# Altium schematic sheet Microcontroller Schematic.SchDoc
size A; SheetNumber: 1; SheetTotal: 1
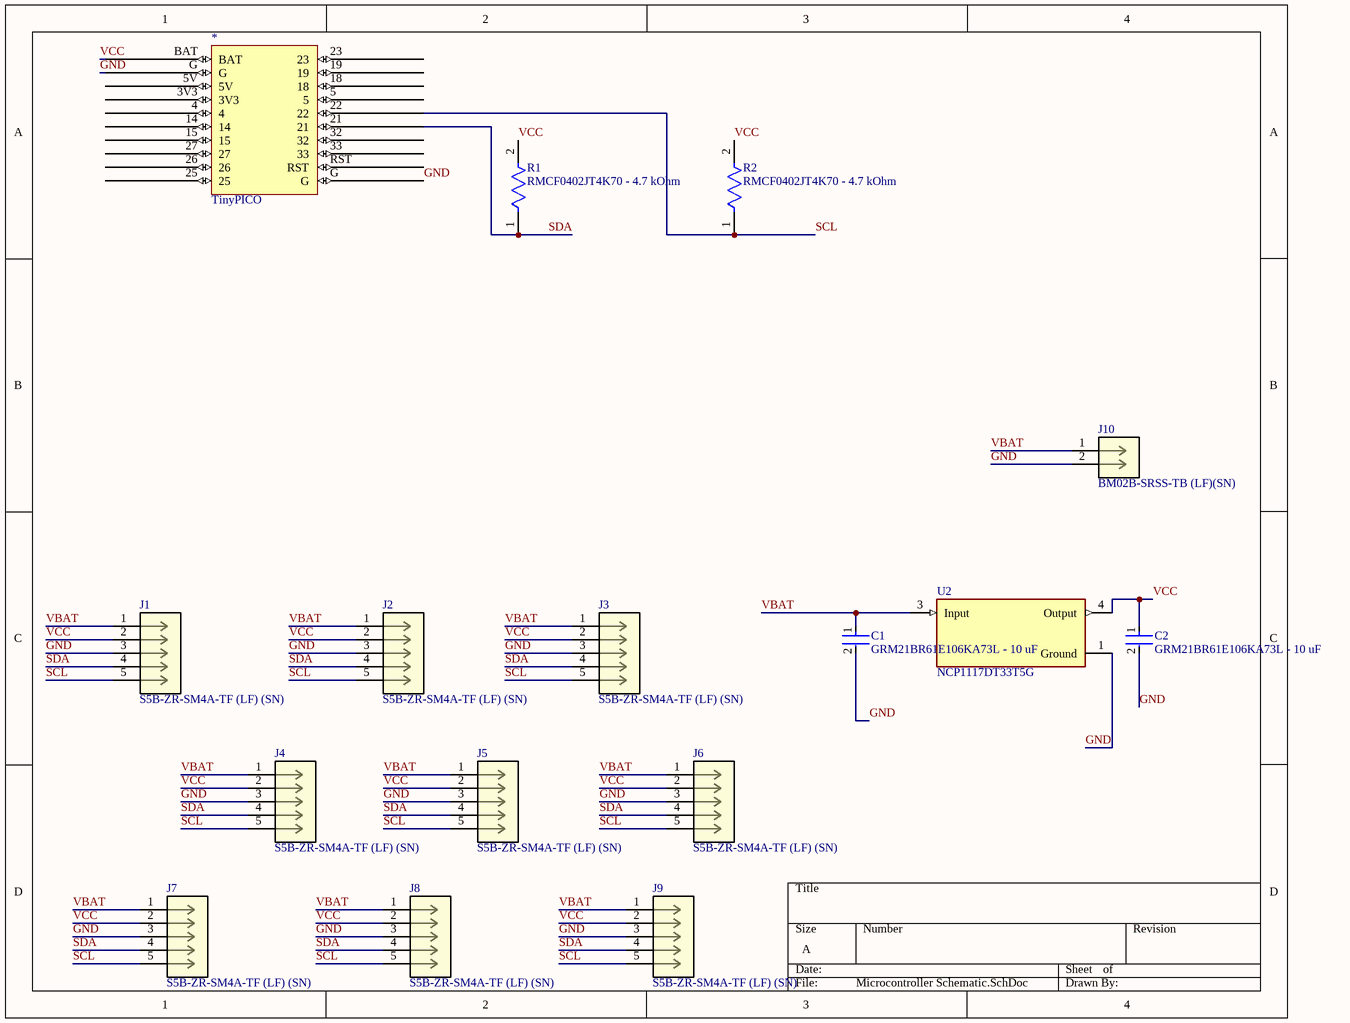
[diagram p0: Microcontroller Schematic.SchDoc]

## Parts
*  TinyPICO  [TinyPICO Board]
C1  GRM21BR61E106KA73L - 10 uF  [FP-GRM21B-0_15-IPC_C]
C2  GRM21BR61E106KA73L - 10 uF  [FP-GRM21B-0_15-IPC_C]
J1  S5B-ZR-SM4A-TF (LF) (SN)  [CONN_S5B-ZR-SM4A-TF_JST]
J2  S5B-ZR-SM4A-TF (LF) (SN)  [CONN_S5B-ZR-SM4A-TF_JST]
J3  S5B-ZR-SM4A-TF (LF) (SN)  [CONN_S5B-ZR-SM4A-TF_JST]
J4  S5B-ZR-SM4A-TF (LF) (SN)  [CONN_S5B-ZR-SM4A-TF_JST]
J5  S5B-ZR-SM4A-TF (LF) (SN)  [CONN_S5B-ZR-SM4A-TF_JST]
J6  S5B-ZR-SM4A-TF (LF) (SN)  [CONN_S5B-ZR-SM4A-TF_JST]
J7  S5B-ZR-SM4A-TF (LF) (SN)  [CONN_S5B-ZR-SM4A-TF_JST]
J8  S5B-ZR-SM4A-TF (LF) (SN)  [CONN_S5B-ZR-SM4A-TF_JST]
J9  S5B-ZR-SM4A-TF (LF) (SN)  [CONN_S5B-ZR-SM4A-TF_JST]
J10  BM02B-SRSS-TB (LF)(SN)  [CONN_BM02B-SRSS-TB_JST]
R1  RMCF0402JT4K70 - 4.7 kOhm  [FP-RMCF0402-MFG]
R2  RMCF0402JT4K70 - 4.7 kOhm  [FP-RMCF0402-MFG]
U2  NCP1117DT33T5G  [FP-369C-MFG]

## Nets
GND: *.G C1.2 C2.2 J1.3 J2.3 J3.3 J4.3 J5.3 J6.3 J7.3 J8.3 J9.3 J10.2 U2.1(Ground)
SCL: *.22 J1.5 J2.5 J3.5 J4.5 J5.5 J6.5 J7.5 J8.5 J9.5 R2.1
SDA: *.21 J1.4 J2.4 J3.4 J4.4 J5.4 J6.4 J7.4 J8.4 J9.4 R1.1
VBAT: C1.1 J1.1 J2.1 J3.1 J4.1 J5.1 J6.1 J7.1 J8.1 J9.1 J10.1 U2.3(Input)
VCC: *.BAT C2.1 J1.2 J2.2 J3.2 J4.2 J5.2 J6.2 J7.2 J8.2 J9.2 R1.2 R2.2 U2.4(Output)

Not connected (* = marked no-connect by the designer): * 3V3 4 5 5V 14 15 18 19 23 25 26 27 32 33 RST

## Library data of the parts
C1 C2 = CMP-2007-03541-2: Chip Multilayer Ceramic Capacitors for General Purpose, 0805, 10uF, X5R, 15%, 10%, 25V
J1-J9 = S5B-ZR-SM4A-TF (LF) (SN): No Description Available; Mfr_Name: JST
J10 = BM02B-SRSS-TB (LF)(SN): No Description Available; Mfr_Name: JST
R1 R2 = CMP-2000-06988-2: 4.7kΩ ±5% 0.063W 0402 Thick Film Chip Resistor AEC-Q200 compliant; Resistance: 4.7kR; Power Rating: 63mW; Temperature Coefficient: 100ppm/°C
U2 = CMP-07128-000023-2: IC REG LINEAR 3.3V 1A DPAK; Polarity: Positive; Input Bias Current: 6mA; Quiescent Current: 10mA; Output Type: Fixed; Number of Outputs: 1; Output Voltage Accuracy: 1%; Max Input Voltage: 20V; Dropout Voltage: 1.07V; Reference Voltage: 1.27V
